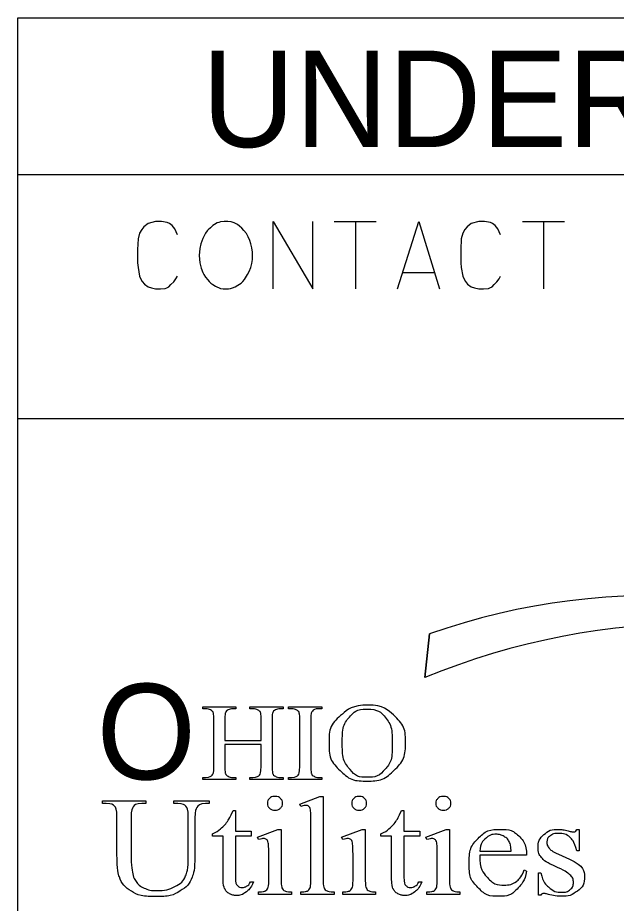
# Model space of a CAD drawing. Extents: x -9.1 to 34, y -3.1 to 22.
# Drawn here: x 3.186 to 4.427, y 3.601 to 5.437 of the extents above; entities that cross this region are included whole.
import ezdxf

# ---------------------------------------------------------------- set-up
doc = ezdxf.new("R2010")
doc.units = 0
doc.layers.add('SH_Data', color=7, linetype='Continuous')

msp = doc.modelspace()

# ---------------------------------------------------------------- linework, layer by layer
at = {"layer": 'SH_Data'}
for p, q in [((3.1861, 5.1116), (8.3861, 5.1116)), ((3.8424, 5.0146), (3.9294, 5.0146)), ((3.8864, 5.0146), (3.8864, 4.8746)), ((4.2326, 5.0146), (4.3196, 5.0146)), ((4.2766, 5.0146), (4.2766, 4.8746)), ((4.0496, 4.9076), (3.9845, 4.9076)), ((3.1861, 4.6057), (8.3861, 4.6057)), ((4.0403, 4.1596), (4.0305, 4.0688))]:
    msp.add_line(p, q, dxfattribs=at)
msp.add_lwpolyline([(3.1861, 5.4367), (8.3861, 5.4367), (8.3861, 2.3367), (3.1861, 2.3367)], close=True, dxfattribs=at)
msp.add_lwpolyline([(3.1861, 5.4367), (8.3861, 5.4367), (8.3861, 2.3367), (3.1861, 2.3367)], close=True, dxfattribs=at)
for points in [[(3.5172, 4.987), (3.5117, 4.9991), (3.5061, 5.0057), (3.5006, 5.0101), (3.4962, 5.0123), (3.4841, 5.0146), (3.472, 5.0146), (3.4566, 5.0101), (3.4477, 5.0035), (3.4433, 4.998), (3.4389, 4.9903), (3.4356, 4.9782), (3.4345, 4.9561), (3.4345, 4.9396), (3.4345, 4.9286), (3.4356, 4.9187), (3.4389, 4.901), (3.44, 4.8977), (3.4444, 4.89), (3.4488, 4.8845), (3.4566, 4.879), (3.4632, 4.8768), (3.472, 4.8746), (3.4819, 4.8746), (3.4918, 4.8757), (3.4951, 4.8768), (3.4995, 4.879), (3.5039, 4.8834), (3.5095, 4.8889), (3.5139, 4.8955), (3.5172, 4.901)], [(3.6065, 5.0135), (3.6031, 5.0123), (3.5999, 5.0113), (3.5943, 5.0079), (3.591, 5.0057), (3.5855, 5.0013), (3.5811, 4.9969), (3.5789, 4.9947), (3.5756, 4.9903), (3.5701, 4.9793), (3.5657, 4.9683), (3.5635, 4.9583), (3.5624, 4.944), (3.5635, 4.9286), (3.5668, 4.9176), (3.5701, 4.9087), (3.5723, 4.9043), (3.5756, 4.8988), (3.58, 4.8933), (3.5833, 4.89), (3.5866, 4.8867), (3.591, 4.8834), (3.5965, 4.8801), (3.6065, 4.8757), (3.612, 4.8746), (3.623, 4.8746), (3.6274, 4.8757), (3.6318, 4.8768), (3.6373, 4.879), (3.6428, 4.8823), (3.6461, 4.8845), (3.6494, 4.8867), (3.6528, 4.89), (3.6561, 4.8944), (3.6583, 4.8977), (3.6605, 4.901), (3.6627, 4.9043), (3.666, 4.9109), (3.6693, 4.9187), (3.6715, 4.9275), (3.6726, 4.9352), (3.6726, 4.9363), (3.6726, 4.944), (3.6726, 4.9506), (3.6715, 4.9594), (3.6693, 4.9683), (3.6671, 4.9749), (3.6638, 4.9826), (3.6605, 4.9892), (3.655, 4.9958), (3.6506, 5.0002), (3.6461, 5.0046), (3.6417, 5.0079), (3.6351, 5.0113), (3.6285, 5.0135), (3.6219, 5.0146), (3.6142, 5.0146), (3.6065, 5.0135)], [(3.7156, 4.8746), (3.7156, 5.0146), (3.7983, 4.8746), (3.7983, 5.0146)], [(3.9735, 4.8746), (4.0176, 5.0146), (4.0606, 4.8746)], [(4.1873, 4.987), (4.1818, 4.9991), (4.1763, 5.0057), (4.1708, 5.0101), (4.1664, 5.0123), (4.1543, 5.0146), (4.1422, 5.0146), (4.1267, 5.0101), (4.1179, 5.0035), (4.1135, 4.998), (4.1091, 4.9903), (4.1058, 4.9782), (4.1047, 4.9561), (4.1047, 4.9396), (4.1047, 4.9286), (4.1058, 4.9187), (4.1091, 4.901), (4.1102, 4.8977), (4.1146, 4.89), (4.119, 4.8845), (4.1267, 4.879), (4.1333, 4.8768), (4.1422, 4.8746), (4.1521, 4.8746), (4.162, 4.8757), (4.1653, 4.8768), (4.1697, 4.879), (4.1741, 4.8834), (4.1796, 4.8889), (4.1841, 4.8955), (4.1873, 4.901)], [(4.0305, 4.0688), (4.0403, 4.1596)], [(3.5753, 4.0044), (3.5696, 4.0044), (3.5696, 4.0085), (3.6387, 4.0085), (3.6387, 4.0044), (3.6329, 4.0044)], [(3.6734, 4.0044), (3.6676, 4.0044), (3.6676, 4.0085), (3.7367, 4.0085), (3.7367, 4.0044), (3.731, 4.0044)], [(3.7535, 4.0044), (3.7478, 4.0044), (3.7478, 4.0085), (3.8169, 4.0085), (3.8169, 4.0044), (3.8111, 4.0044)], [(3.5927, 3.8846), (3.5927, 3.9818)], [(3.6156, 3.9386), (3.6908, 3.9386), (3.6908, 3.9818)], [(3.6156, 3.9818), (3.6156, 3.9386)], [(3.7136, 3.9818), (3.7136, 3.8846)], [(3.7709, 3.8846), (3.7709, 3.9818)], [(3.7938, 3.9818), (3.7938, 3.8846)], [(3.6908, 3.8846), (3.6908, 3.9304), (3.6156, 3.9304), (3.6156, 3.8846)], [(3.6329, 3.8619), (3.6387, 3.8619), (3.6387, 3.8579), (3.5696, 3.8579), (3.5696, 3.8619), (3.5753, 3.8619)], [(3.731, 3.8619), (3.7367, 3.8619), (3.7367, 3.8579), (3.6676, 3.8579), (3.6676, 3.8619), (3.6734, 3.8619)], [(3.8169, 3.8619), (3.8169, 3.8579), (3.7478, 3.8579), (3.7478, 3.8619), (3.7535, 3.8619)], [(3.8111, 3.8619), (3.8169, 3.8619)], [(3.7735, 3.8015), (3.7709, 3.8068), (3.8127, 3.8227), (3.8196, 3.8227)], [(3.8196, 3.8227), (3.8196, 3.6492)], [(3.3695, 3.808), (3.3617, 3.808), (3.3617, 3.8133), (3.4516, 3.8133), (3.4516, 3.808), (3.4436, 3.808)], [(3.51, 3.808), (3.51, 3.8133), (3.5832, 3.8133), (3.5832, 3.808), (3.5754, 3.808)], [(3.5178, 3.808), (3.51, 3.808)], [(3.6328, 3.7935), (3.6375, 3.7935)], [(3.6375, 3.7935), (3.6375, 3.7504), (3.6704, 3.7504), (3.6704, 3.7405), (3.6375, 3.7405), (3.6375, 3.6556)], [(3.982, 3.7935), (3.9868, 3.7935)], [(3.9868, 3.7935), (3.9868, 3.7504), (4.0196, 3.7504), (4.0196, 3.7405), (3.9868, 3.7405), (3.9868, 3.6556)], [(3.3919, 3.7033), (3.3919, 3.7789)], [(3.4213, 3.7789), (3.4213, 3.6947)], [(3.5397, 3.7006), (3.5397, 3.7789)], [(3.5535, 3.7778), (3.5535, 3.6993)], [(3.7941, 3.6492), (3.7941, 3.768)], [(3.6121, 3.6524), (3.6121, 3.7405), (3.5898, 3.7405), (3.5898, 3.7452)], [(3.6854, 3.733), (3.6832, 3.7383), (3.7256, 3.7542), (3.7323, 3.7542)], [(3.7323, 3.7542), (3.7323, 3.6492)], [(3.86, 3.733), (3.8578, 3.7383), (3.9002, 3.7542), (3.9069, 3.7542)], [(3.9069, 3.7542), (3.9069, 3.6492)], [(3.9613, 3.6524), (3.9613, 3.7405), (3.939, 3.7405), (3.939, 3.7452)], [(4.0346, 3.733), (4.0324, 3.7383), (4.0748, 3.7542), (4.0815, 3.7542)], [(4.0815, 3.7542), (4.0815, 3.6492)], [(4.3506, 3.7542), (4.3506, 3.7096), (4.3455, 3.7096)], [(4.3455, 3.7542), (4.3506, 3.7542)], [(4.144, 3.7093), (4.2093, 3.7093)], [(3.7068, 3.6492), (3.7068, 3.6995)], [(3.8814, 3.6492), (3.8814, 3.6995)], [(4.0561, 3.6492), (4.0561, 3.6995)], [(4.2412, 3.7011), (4.144, 3.7011)], [(4.3076, 3.7027), (4.33, 3.6926)], [(4.2364, 3.6702), (4.2412, 3.6674)], [(4.2711, 3.6177), (4.266, 3.6177), (4.266, 3.6644), (4.2711, 3.6644)], [(3.6688, 3.6455), (3.6747, 3.6455)], [(4.018, 3.6455), (4.024, 3.6455)], [(3.7535, 3.6248), (3.7535, 3.6196), (3.6854, 3.6196), (3.6854, 3.6248)], [(3.8424, 3.6248), (3.8424, 3.6196), (3.7733, 3.6196), (3.7733, 3.6248)], [(3.9282, 3.6248), (3.9282, 3.6196), (3.86, 3.6196), (3.86, 3.6248)], [(4.1028, 3.6248), (4.1028, 3.6196), (4.0347, 3.6196), (4.0347, 3.6248)]]:
    msp.add_lwpolyline(points, dxfattribs=at)
for centre, major_axis, start_param, end_param in [((4.5071, 3.1268), (1.2569, 0), 0.997452, 1.951337), ((4.5071, 3.1268), (1.2569, 0), 0.997452, 1.951337), ((4.6009, 2.9941), (1.3416, 0), 1.117038, 2.009874), ((4.6009, 2.9941), (1.3416, 0), 1.117038, 2.009874)]:
    msp.add_ellipse(centre, major_axis=major_axis, ratio=0.88499, start_param=start_param, end_param=end_param, dxfattribs=at)
for points in [[(3.5927, 3.9818), (3.5927, 3.9933), (3.5912, 3.997), (3.59, 3.9998), (3.5863, 4.0018), (3.581, 4.0044), (3.5753, 4.0044)], [(3.6329, 4.0044), (3.6272, 4.0044), (3.6221, 4.0019), (3.6184, 4.0001), (3.617, 3.9965), (3.6156, 3.9929), (3.6156, 3.9818)], [(3.6908, 3.9818), (3.6908, 3.9933), (3.6892, 3.997), (3.688, 3.9998), (3.6842, 4.0018), (3.6791, 4.0044), (3.6734, 4.0044)], [(3.731, 4.0044), (3.7253, 4.0044), (3.7202, 4.0019), (3.7163, 4.0001), (3.715, 3.9965), (3.7136, 3.9929), (3.7136, 3.9818)], [(3.7709, 3.9818), (3.7709, 3.9933), (3.7694, 3.997), (3.7682, 3.9998), (3.7645, 4.0018), (3.7593, 4.0044), (3.7535, 4.0044)], [(3.8111, 4.0044), (3.8013, 4.0044), (3.7968, 3.999), (3.7938, 3.9954), (3.7938, 3.9818)], [(3.9125, 4.012), (3.9439, 4.012), (3.967, 3.9897), (3.9901, 3.9674), (3.9901, 3.9341), (3.9901, 3.8998), (3.9668, 3.8771), (3.9436, 3.8544), (3.9105, 3.8544), (3.8772, 3.8544), (3.8544, 3.8765), (3.8317, 3.8986), (3.8317, 3.9337), (3.8317, 3.9696), (3.8579, 3.9923), (3.8807, 4.012), (3.9125, 4.012)], [(3.9102, 4.0038), (3.8885, 4.0038), (3.8754, 3.9888), (3.8591, 3.9702), (3.8591, 3.9342), (3.8591, 3.8973), (3.876, 3.8774), (3.889, 3.8623), (3.9103, 3.8623), (3.9331, 3.8623), (3.9479, 3.8789), (3.9628, 3.8954), (3.9628, 3.9311), (3.9628, 3.9697), (3.9464, 3.9887), (3.9333, 4.0038), (3.9102, 4.0038)], [(3.5753, 3.8619), (3.5853, 3.8619), (3.5899, 3.8674), (3.5927, 3.871), (3.5927, 3.8846)], [(3.6156, 3.8846), (3.6156, 3.8731), (3.6171, 3.8694), (3.6183, 3.8666), (3.6221, 3.8646), (3.6272, 3.8619), (3.6329, 3.8619)], [(3.6734, 3.8619), (3.6832, 3.8619), (3.6878, 3.8674), (3.6908, 3.871), (3.6908, 3.8846)], [(3.7136, 3.8846), (3.7136, 3.8731), (3.7152, 3.8694), (3.7163, 3.8666), (3.72, 3.8646), (3.7253, 3.8619), (3.731, 3.8619)], [(3.7535, 3.8619), (3.7636, 3.8619), (3.7681, 3.8674), (3.7709, 3.871), (3.7709, 3.8846)], [(3.7938, 3.8846), (3.7938, 3.8731), (3.7953, 3.8694), (3.7965, 3.8666), (3.8003, 3.8646), (3.8054, 3.8619), (3.8111, 3.8619)], [(3.7196, 3.8227), (3.726, 3.8227), (3.7305, 3.8185), (3.735, 3.8143), (3.735, 3.8083), (3.735, 3.8024), (3.7305, 3.7981), (3.726, 3.7938), (3.7196, 3.7938), (3.7131, 3.7938), (3.7085, 3.7981), (3.704, 3.8024), (3.704, 3.8083), (3.704, 3.8143), (3.7085, 3.8185), (3.713, 3.8227), (3.7196, 3.8227)], [(3.8942, 3.8227), (3.9006, 3.8227), (3.9051, 3.8185), (3.9096, 3.8143), (3.9096, 3.8083), (3.9096, 3.8024), (3.9051, 3.7981), (3.9006, 3.7938), (3.8942, 3.7938), (3.8877, 3.7938), (3.8832, 3.7981), (3.8786, 3.8024), (3.8786, 3.8083), (3.8786, 3.8143), (3.8831, 3.8185), (3.8876, 3.8227), (3.8942, 3.8227)], [(4.0688, 3.8227), (4.0752, 3.8227), (4.0797, 3.8185), (4.0842, 3.8143), (4.0842, 3.8083), (4.0842, 3.8024), (4.0797, 3.7981), (4.0752, 3.7938), (4.0688, 3.7938), (4.0624, 3.7938), (4.0578, 3.7981), (4.0532, 3.8024), (4.0532, 3.8083), (4.0532, 3.8143), (4.0577, 3.8185), (4.0622, 3.8227), (4.0688, 3.8227)], [(3.3919, 3.7789), (3.3919, 3.7968), (3.3866, 3.8024), (3.3813, 3.808), (3.3695, 3.808)], [(3.4436, 3.808), (3.4307, 3.808), (3.4252, 3.8004), (3.4213, 3.7953), (3.4213, 3.7789)], [(3.5397, 3.7789), (3.5397, 3.7971), (3.5354, 3.8017), (3.5295, 3.808), (3.5178, 3.808)], [(3.5754, 3.808), (3.5632, 3.808), (3.5567, 3.7984), (3.5535, 3.794), (3.5535, 3.7778)], [(3.7941, 3.768), (3.7941, 3.79), (3.7931, 3.7951), (3.792, 3.8001), (3.7896, 3.802), (3.7873, 3.8038), (3.7836, 3.8038), (3.7796, 3.8038), (3.7735, 3.8015)], [(3.5898, 3.7452), (3.5983, 3.7483), (3.6071, 3.7558), (3.6159, 3.7633), (3.6229, 3.7736), (3.6264, 3.779), (3.6328, 3.7935)], [(3.939, 3.7452), (3.9475, 3.7483), (3.9563, 3.7558), (3.9651, 3.7633), (3.9721, 3.7736), (3.9757, 3.779), (3.982, 3.7935)], [(4.2412, 3.6674), (4.238, 3.6477), (4.2225, 3.6317), (4.207, 3.6156), (4.1837, 3.6156), (4.1583, 3.6156), (4.1403, 3.634), (4.1223, 3.6523), (4.1223, 3.6832), (4.1223, 3.7167), (4.1408, 3.7355), (4.1593, 3.7542), (4.1872, 3.7542), (4.2108, 3.7542), (4.226, 3.7398), (4.2412, 3.7253), (4.2412, 3.7011)], [(4.2711, 3.6644), (4.2754, 3.6443), (4.2874, 3.6342), (4.2995, 3.624), (4.3145, 3.624), (4.325, 3.624), (4.3317, 3.6298), (4.3383, 3.6356), (4.3383, 3.6437), (4.3383, 3.6536), (4.3309, 3.6603), (4.3236, 3.667), (4.3013, 3.6772), (4.2791, 3.6875), (4.2722, 3.6958), (4.2653, 3.7039), (4.2653, 3.7164), (4.2653, 3.7325), (4.2772, 3.7434), (4.2891, 3.7542), (4.3079, 3.7542), (4.3162, 3.7542), (4.328, 3.751), (4.3358, 3.7489), (4.3384, 3.7489), (4.3409, 3.7489), (4.3423, 3.7498), (4.3436, 3.7508), (4.3455, 3.7542)], [(4.3455, 3.7096), (4.3397, 3.7307), (4.3306, 3.7383), (4.3214, 3.7458), (4.3074, 3.7458), (4.2966, 3.7458), (4.2901, 3.7406), (4.2835, 3.7353), (4.2835, 3.7289), (4.2835, 3.7209), (4.2883, 3.7151), (4.2931, 3.7093), (4.3076, 3.7027)], [(3.7068, 3.6995), (3.7068, 3.7208), (3.7055, 3.727), (3.7044, 3.7316), (3.7021, 3.7334), (3.6998, 3.7352), (3.6958, 3.7352), (3.6915, 3.7352), (3.6854, 3.733)], [(3.8814, 3.6995), (3.8814, 3.7208), (3.8801, 3.727), (3.879, 3.7316), (3.8767, 3.7334), (3.8744, 3.7352), (3.8704, 3.7352), (3.8661, 3.7352), (3.86, 3.733)], [(4.0561, 3.6995), (4.0561, 3.7208), (4.0547, 3.727), (4.0536, 3.7316), (4.0513, 3.7334), (4.049, 3.7352), (4.045, 3.7352), (4.0407, 3.7352), (4.0346, 3.733)], [(4.2093, 3.7093), (4.2085, 3.7219), (4.206, 3.727), (4.2022, 3.735), (4.1946, 3.7395), (4.187, 3.7441), (4.1786, 3.7441), (4.1659, 3.7441), (4.1558, 3.7349), (4.1457, 3.7257), (4.144, 3.7093)], [(3.5535, 3.6993), (3.5535, 3.6702), (3.5473, 3.6542), (3.5411, 3.6381), (3.5229, 3.6266), (3.5047, 3.6152), (3.4735, 3.6152), (3.4394, 3.6152), (3.4218, 3.6261), (3.4042, 3.6371), (3.3968, 3.6557), (3.3919, 3.6684), (3.3919, 3.7033)], [(3.4213, 3.6947), (3.4213, 3.6834), (3.4235, 3.6688), (3.4258, 3.6543), (3.4316, 3.6462), (3.4374, 3.638), (3.4484, 3.6328), (3.4594, 3.6275), (3.4753, 3.6275), (3.4957, 3.6275), (3.5118, 3.6358), (3.5279, 3.644), (3.5338, 3.6569), (3.5397, 3.6698), (3.5397, 3.7006)], [(4.144, 3.7011), (4.1439, 3.672), (4.1592, 3.6554), (4.1746, 3.6389), (4.1953, 3.6389), (4.2091, 3.6389), (4.2193, 3.6459), (4.2295, 3.653), (4.2364, 3.6702)], [(4.33, 3.6926), (4.3611, 3.6784), (4.3611, 3.6553), (4.3611, 3.6375), (4.3466, 3.6265), (4.3322, 3.6156), (4.3143, 3.6156), (4.3014, 3.6156), (4.2849, 3.6199), (4.2798, 3.6213), (4.2766, 3.6213), (4.2731, 3.6213), (4.2711, 3.6177)], [(3.6375, 3.6556), (3.6375, 3.6428), (3.6415, 3.6384), (3.6454, 3.634), (3.6516, 3.634), (3.6566, 3.634), (3.6614, 3.6369), (3.6662, 3.6398), (3.6688, 3.6455)], [(3.9868, 3.6556), (3.9868, 3.6428), (3.9907, 3.6384), (3.9946, 3.634), (4.0008, 3.634), (4.0058, 3.634), (4.0106, 3.6369), (4.0154, 3.6398), (4.018, 3.6455)], [(3.6747, 3.6455), (3.6693, 3.6315), (3.6595, 3.6244), (3.6496, 3.6174), (3.6392, 3.6174), (3.6321, 3.6174), (3.6253, 3.621), (3.6185, 3.6247), (3.6153, 3.6315), (3.6121, 3.6382), (3.6121, 3.6524)], [(3.6854, 3.6248), (3.6957, 3.6248), (3.6992, 3.6267), (3.7027, 3.6285), (3.7048, 3.6328), (3.7068, 3.6371), (3.7068, 3.6492)], [(3.7323, 3.6492), (3.7323, 3.6369), (3.7342, 3.6329), (3.7361, 3.6288), (3.7399, 3.6268), (3.7436, 3.6248), (3.7535, 3.6248)], [(3.7733, 3.6248), (3.783, 3.6248), (3.7866, 3.6267), (3.7901, 3.6285), (3.7921, 3.6328), (3.7941, 3.6371), (3.7941, 3.6492)], [(3.8196, 3.6492), (3.8196, 3.6369), (3.8215, 3.6329), (3.8235, 3.6289), (3.8275, 3.6269), (3.8315, 3.6248), (3.8424, 3.6248)], [(3.86, 3.6248), (3.8703, 3.6248), (3.8738, 3.6267), (3.8773, 3.6285), (3.8794, 3.6328), (3.8814, 3.6371), (3.8814, 3.6492)], [(3.9069, 3.6492), (3.9069, 3.6369), (3.9088, 3.6329), (3.9107, 3.6288), (3.9145, 3.6268), (3.9182, 3.6248), (3.9282, 3.6248)], [(4.024, 3.6455), (4.0186, 3.6315), (4.0087, 3.6244), (3.9989, 3.6174), (3.9884, 3.6174), (3.9813, 3.6174), (3.9745, 3.621), (3.9677, 3.6247), (3.9645, 3.6315), (3.9613, 3.6382), (3.9613, 3.6524)], [(4.0347, 3.6248), (4.0449, 3.6248), (4.0484, 3.6267), (4.0519, 3.6285), (4.054, 3.6328), (4.0561, 3.6371), (4.0561, 3.6492)], [(4.0815, 3.6492), (4.0815, 3.6369), (4.0834, 3.6329), (4.0854, 3.6288), (4.0891, 3.6268), (4.0928, 3.6248), (4.1028, 3.6248)]]:
    msp.add_open_spline(points, degree=3, dxfattribs=at)

# ---------------------------------------------------------------- texts
for s, height, p in [('UNDERGROUND UTILITIES', 0.2, (3.5679, 5.1686)), ('O', 0.1981, (3.3497, 3.8579))]:
    msp.add_text(s, height=height, dxfattribs=at).set_placement(p)

doc.saveas('drawing.dxf')
